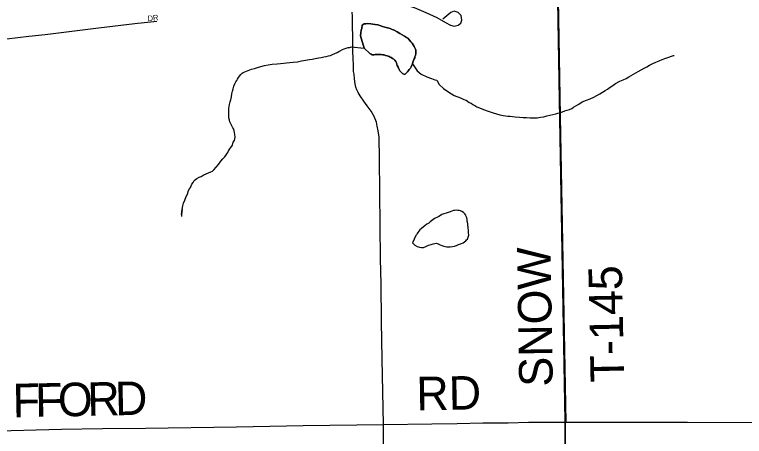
# Model space of a CAD drawing. Extents: x 0 to 34, y 0 to 22.
# Drawn here: x 3.494 to 4.731, y 18.837 to 19.552 of the extents above; entities that cross this region are included whole.
import ezdxf

# ---------------------------------------------------------------- set-up
doc = ezdxf.new("R2010")
doc.units = 0
for name, color, linetype in [('GM_X_Minor_Lake', 7, 'Continuous'), ('GM_X_Minor_River', 7, 'Continuous'), ('GM_X_Township', 7, 'Continuous'), ('GM_X_Township_Road', 7, 'Continuous'), ('GM_X_Township_Road_Text', 7, 'Continuous'), ('GM_X_Township_Subdivision', 7, 'Continuous'), ('GM_X_Township_Subdivision_Text', 7, 'Continuous')]:
    doc.layers.add(name, color=color, linetype=linetype)

msp = doc.modelspace()

# ---------------------------------------------------------------- linework, layer by layer
at = {"layer": 'GM_X_Minor_Lake'}
for points in [[(4.1715, 19.4767), (4.1722, 19.4786), (4.1725, 19.4805), (4.1736, 19.4824), (4.1739, 19.4858), (4.1742, 19.4889), (4.1742, 19.4915), (4.1738, 19.4934), (4.1726, 19.4957), (4.1714, 19.4976), (4.1694, 19.5006), (4.1678, 19.5032), (4.1655, 19.5058), (4.1635, 19.5084), (4.1604, 19.5118), (4.1585, 19.5132), (4.155, 19.5151), (4.1512, 19.5173), (4.1469, 19.5198), (4.1423, 19.5224), (4.1373, 19.5253), (4.1339, 19.5268), (4.1304, 19.5282), (4.1262, 19.5293), (4.1216, 19.5303), (4.1174, 19.5317), (4.1132, 19.5335), (4.1097, 19.5346), (4.1055, 19.5353), (4.1013, 19.5359), (4.0979, 19.5362), (4.093, 19.5365), (4.0895, 19.5364), (4.0865, 19.5364), (4.0831, 19.534), (4.0825, 19.5283), (4.0818, 19.5253), (4.0811, 19.5207), (4.0805, 19.5157), (4.0866, 19.4951)], [(4.0866, 19.4951), (4.0805, 19.5157), (4.0811, 19.5207), (4.0818, 19.5253), (4.0825, 19.5283), (4.0831, 19.534), (4.0865, 19.5364), (4.0895, 19.5364), (4.093, 19.5365), (4.0979, 19.5362), (4.1013, 19.5359), (4.1055, 19.5353), (4.1097, 19.5346), (4.1132, 19.5335), (4.1174, 19.5317), (4.1216, 19.5303), (4.1262, 19.5293), (4.1304, 19.5282), (4.1339, 19.5268), (4.1373, 19.5253), (4.1423, 19.5224), (4.1469, 19.5198), (4.1512, 19.5173), (4.155, 19.5151), (4.1585, 19.5132), (4.1604, 19.5118), (4.1635, 19.5084), (4.1655, 19.5058), (4.1678, 19.5032), (4.1694, 19.5006), (4.1714, 19.4976), (4.1726, 19.4957), (4.1738, 19.4934), (4.1742, 19.4915), (4.1742, 19.4889), (4.1739, 19.4858), (4.1736, 19.4824), (4.1725, 19.4805), (4.1722, 19.4786), (4.1715, 19.4767), (4.1704, 19.474), (4.1693, 19.4713), (4.1686, 19.4682), (4.1675, 19.4659), (4.166, 19.4632), (4.1649, 19.4613), (4.1631, 19.459), (4.1616, 19.4571), (4.1601, 19.4548), (4.1579, 19.4528), (4.1553, 19.4505), (4.1514, 19.4523), (4.1491, 19.4545), (4.1471, 19.4568), (4.1456, 19.4598), (4.144, 19.4628), (4.1428, 19.4658), (4.142, 19.468), (4.1412, 19.4699), (4.14, 19.4722), (4.1384, 19.4744), (4.1368, 19.4763), (4.1349, 19.4774), (4.1326, 19.4789), (4.1307, 19.4796), (4.1288, 19.4807), (4.1257, 19.4821), (4.123, 19.4828), (4.1207, 19.4835), (4.1184, 19.4839), (4.1154, 19.4842), (4.1123, 19.4845), (4.1097, 19.4844), (4.1074, 19.4844), (4.1055, 19.484), (4.1036, 19.4839), (4.1002, 19.4839), (4.0982, 19.4846), (4.0963, 19.4857), (4.0866, 19.4951)], [(4.0866, 19.4951), (4.0963, 19.4857), (4.0982, 19.4846), (4.1002, 19.4839), (4.1036, 19.4839), (4.1055, 19.484), (4.1074, 19.4844), (4.1097, 19.4844), (4.1123, 19.4845), (4.1154, 19.4842), (4.1184, 19.4839), (4.1207, 19.4835), (4.123, 19.4828), (4.1257, 19.4821), (4.1288, 19.4807), (4.1307, 19.4796), (4.1326, 19.4789), (4.1349, 19.4774), (4.1368, 19.4763), (4.1384, 19.4744), (4.14, 19.4722), (4.1412, 19.4699), (4.142, 19.468), (4.1428, 19.4658), (4.144, 19.4628), (4.1456, 19.4598), (4.1471, 19.4568), (4.1491, 19.4545), (4.1514, 19.4523), (4.1553, 19.4505), (4.1579, 19.4528), (4.1601, 19.4548), (4.1616, 19.4571), (4.1631, 19.459), (4.1649, 19.4613), (4.166, 19.4632), (4.1675, 19.4659), (4.1686, 19.4682), (4.1693, 19.4713), (4.1704, 19.474), (4.1715, 19.4767)], [(4.2614, 19.202), (4.2609, 19.2046), (4.2605, 19.2077), (4.2597, 19.2099), (4.2589, 19.2118), (4.2573, 19.2144), (4.255, 19.2167), (4.2519, 19.2181), (4.25, 19.2192), (4.2477, 19.2199), (4.2454, 19.2202), (4.2423, 19.2206), (4.2405, 19.2201), (4.2378, 19.2197), (4.2352, 19.2189), (4.2321, 19.2177), (4.2287, 19.2165), (4.2253, 19.2156), (4.2216, 19.2144), (4.2185, 19.2132), (4.2159, 19.2116), (4.2129, 19.21), (4.2099, 19.2081), (4.2069, 19.2069), (4.2031, 19.2041), (4.2009, 19.2026), (4.1986, 19.2006), (4.196, 19.1987), (4.193, 19.1967), (4.19, 19.1947), (4.1837, 19.1896), (4.1811, 19.1869), (4.1792, 19.185), (4.1777, 19.1827), (4.1762, 19.1807), (4.1751, 19.1788), (4.174, 19.1777), (4.174, 19.1773), (4.1686, 19.165)], [(4.1686, 19.165), (4.1725, 19.1613), (4.1763, 19.1591), (4.1802, 19.1576), (4.1836, 19.1573), (4.1874, 19.1574), (4.1912, 19.159), (4.1957, 19.161), (4.2002, 19.1623), (4.2036, 19.1635), (4.2063, 19.1639), (4.2093, 19.1644), (4.2131, 19.1629), (4.2154, 19.1618), (4.2185, 19.1604), (4.2216, 19.1597), (4.2239, 19.159), (4.2269, 19.1583), (4.2296, 19.1583), (4.2326, 19.1584), (4.2361, 19.1589), (4.2395, 19.1597), (4.2429, 19.1605), (4.2462, 19.1625), (4.2515, 19.1641), (4.2546, 19.1653), (4.2587, 19.1685), (4.2602, 19.1704), (4.262, 19.1716), (4.2638, 19.1781), (4.2637, 19.1823), (4.2633, 19.1845), (4.2632, 19.1868), (4.2628, 19.1902), (4.2627, 19.1921), (4.2623, 19.194), (4.2622, 19.1974), (4.2618, 19.2001), (4.2614, 19.202), (4.2609, 19.2046), (4.2605, 19.2077), (4.2597, 19.2099), (4.2589, 19.2118), (4.2573, 19.2144), (4.255, 19.2167), (4.2519, 19.2181), (4.25, 19.2192), (4.2477, 19.2199), (4.2454, 19.2202), (4.2423, 19.2206), (4.2405, 19.2201), (4.2378, 19.2197), (4.2352, 19.2189), (4.2321, 19.2177), (4.2287, 19.2165), (4.2253, 19.2156), (4.2216, 19.2144), (4.2185, 19.2132), (4.2159, 19.2116), (4.2129, 19.21), (4.2099, 19.2081), (4.2069, 19.2069), (4.2031, 19.2041), (4.2009, 19.2026), (4.1986, 19.2006), (4.196, 19.1987), (4.193, 19.1967), (4.19, 19.1947), (4.1837, 19.1896), (4.1811, 19.1869), (4.1792, 19.185), (4.1777, 19.1827), (4.1762, 19.1807), (4.1751, 19.1788), (4.174, 19.1777), (4.174, 19.1773), (4.1686, 19.165)], [(4.1686, 19.165), (4.1725, 19.1613), (4.1763, 19.1591), (4.1802, 19.1576), (4.1836, 19.1573), (4.1874, 19.1574), (4.1912, 19.159), (4.1957, 19.161), (4.2002, 19.1623), (4.2036, 19.1635), (4.2063, 19.1639), (4.2093, 19.1644), (4.2131, 19.1629), (4.2154, 19.1618), (4.2185, 19.1604), (4.2216, 19.1597), (4.2239, 19.159), (4.2269, 19.1583), (4.2296, 19.1583), (4.2326, 19.1584), (4.2361, 19.1589), (4.2395, 19.1597), (4.2429, 19.1605), (4.2462, 19.1625), (4.2515, 19.1641), (4.2546, 19.1653), (4.2587, 19.1685), (4.2602, 19.1704), (4.262, 19.1716), (4.2638, 19.1781), (4.2637, 19.1823), (4.2633, 19.1845), (4.2632, 19.1868), (4.2628, 19.1902), (4.2627, 19.1921), (4.2623, 19.194), (4.2622, 19.1974), (4.2618, 19.2001), (4.2614, 19.202)]]:
    msp.add_lwpolyline(points, dxfattribs=at)
at = {"layer": 'GM_X_Minor_River'}
for points in [[(4.0437, 19.4891), (4.046, 19.4903), (4.0498, 19.4926), (4.0528, 19.4938), (4.0562, 19.4951), (4.0596, 19.4959), (4.0622, 19.4963), (4.0645, 19.4971), (4.0866, 19.4951)], [(3.7774, 19.2097), (3.7779, 19.2218), (3.7773, 19.2131), (3.7779, 19.2218), (3.7792, 19.2276), (3.7807, 19.2322), (3.7828, 19.2375), (3.785, 19.2437), (3.7875, 19.249), (3.7886, 19.2525), (3.7908, 19.2567), (3.7923, 19.259), (3.7934, 19.2617), (3.7944, 19.2648), (3.7967, 19.2671), (3.7985, 19.2706), (3.803, 19.2741), (3.8067, 19.2764), (3.8101, 19.2777), (3.812, 19.2785), (3.815, 19.2804), (3.8188, 19.282), (3.8229, 19.284), (3.8267, 19.2856), (3.8293, 19.2868), (3.8316, 19.2891), (3.8398, 19.2977), (3.8438, 19.3035), (3.8472, 19.3073), (3.8498, 19.3104), (3.852, 19.3131), (3.8538, 19.3158), (3.8553, 19.3182), (3.8568, 19.3212), (3.859, 19.3247), (3.8608, 19.3266), (3.8634, 19.3309), (3.8648, 19.3358), (3.867, 19.3386), (3.8677, 19.3443), (3.8676, 19.3488), (3.8671, 19.3519), (3.8663, 19.3549), (3.8655, 19.3579), (3.8643, 19.3602), (3.8627, 19.3624), (3.8611, 19.3658), (3.8591, 19.3699), (3.8583, 19.3729), (3.8575, 19.3771), (3.8574, 19.3817), (3.8573, 19.3858), (3.8575, 19.3927), (3.8585, 19.3995), (3.8595, 19.4041), (3.8606, 19.4076), (3.8617, 19.4125), (3.8623, 19.4175), (3.8634, 19.4221), (3.8644, 19.4263), (3.8658, 19.4305), (3.8673, 19.4343), (3.8691, 19.4378), (3.8706, 19.4401), (3.872, 19.4424), (3.8739, 19.4451), (3.8754, 19.4478), (3.8776, 19.4505), (3.8798, 19.4528), (3.8817, 19.454), (3.8957, 19.4593), (3.9006, 19.4605), (3.9059, 19.4621), (3.9115, 19.4642), (3.9176, 19.4658), (3.924, 19.4667), (3.9305, 19.468), (3.9392, 19.4686), (3.9449, 19.4691), (3.9502, 19.4696), (3.9551, 19.4701), (3.9605, 19.4705), (3.9665, 19.4711), (3.9734, 19.472), (3.9806, 19.4736), (3.9874, 19.4749), (3.9938, 19.4758), (3.9984, 19.4763), (4.0014, 19.4768), (4.0037, 19.4772), (4.0063, 19.478), (4.0097, 19.4788), (4.0139, 19.4793), (4.0181, 19.4802), (4.0222, 19.481), (4.026, 19.4819), (4.0294, 19.4827), (4.0328, 19.4843), (4.037, 19.4859), (4.0407, 19.4879), (4.0437, 19.4891)], [(4.1686, 19.4682), (4.1764, 19.4566), (4.1834, 19.4511), (4.1926, 19.4463), (4.2007, 19.4435), (4.2064, 19.4413), (4.2099, 19.4406), (4.2135, 19.4335), (4.2208, 19.4264), (4.2301, 19.4206), (4.2393, 19.4147), (4.2501, 19.4107), (4.2555, 19.4082), (4.2593, 19.4071), (4.262, 19.4053), (4.2647, 19.4031), (4.2678, 19.4016), (4.2705, 19.3998), (4.2739, 19.3976), (4.2778, 19.3958), (4.2905, 19.3903), (4.2951, 19.3889), (4.3, 19.3871), (4.3054, 19.3853), (4.3108, 19.3836), (4.3165, 19.3818), (4.3219, 19.3808), (4.3264, 19.3801), (4.3302, 19.3798), (4.3341, 19.3795), (4.3379, 19.3792), (4.3424, 19.3785), (4.3501, 19.378), (4.3558, 19.3777), (4.3619, 19.3775), (4.368, 19.3772), (4.374, 19.377), (4.3798, 19.3771), (4.3854, 19.378), (4.3911, 19.3788), (4.396, 19.3805), (4.4013, 19.3817), (4.4063, 19.3826), (4.4112, 19.3838), (4.4146, 19.3847), (4.4184, 19.3855), (4.4225, 19.3871), (4.4267, 19.3887), (4.4308, 19.39), (4.4346, 19.3912), (4.4384, 19.3928), (4.4414, 19.3948), (4.4451, 19.3971), (4.4504, 19.3999), (4.456, 19.4038), (4.4636, 19.4066), (4.4696, 19.4094), (4.4756, 19.4122), (4.4809, 19.4146), (4.4862, 19.4174), (4.4907, 19.4205), (4.4952, 19.4233), (4.4989, 19.4257), (4.5034, 19.4288), (4.5079, 19.4319), (4.5128, 19.4351), (4.5199, 19.439), (4.5256, 19.4414), (4.5309, 19.4438), (4.5354, 19.4466), (4.5512, 19.4557), (4.556, 19.4584), (4.5609, 19.4612), (4.5658, 19.4636), (4.5703, 19.466), (4.5745, 19.4683), (4.5809, 19.4711), (4.5865, 19.4735), (4.5918, 19.4759), (4.5979, 19.478), (4.6031, 19.4796), (4.6073, 19.4812), (4.6107, 19.4824), (4.6118, 19.4825)]]:
    msp.add_lwpolyline(points, dxfattribs=at)
at = {"layer": 'GM_X_Township'}
for points in [[(9.1622, 19.7691), (8.817, 19.7645), (7.8005, 19.7395), (6.782, 19.7315), (5.8028, 19.7101), (4.4134, 19.6764), (4.4176, 19.4076), (4.4274, 18.8628), (4.4298, 18.3764)], [(4.4298, 18.3764), (4.4274, 18.8628), (4.4176, 19.4076), (4.4134, 19.6764), (4.0516, 19.6654), (3.407, 19.6503), (2.3622, 19.6335)]]:
    msp.add_lwpolyline(points, dxfattribs=at)
at = {"layer": 'GM_X_Township_Road'}
for points in [[(4.4288, 18.8614), (4.4191, 19.3797), (4.4149, 19.6447)], [(4.1191, 18.8574), (4.1171, 18.9681), (4.1159, 19.0321), (4.1156, 19.0958), (4.1145, 19.1381), (4.1124, 19.3074), (4.1119, 19.344), (4.1105, 19.3548), (4.1089, 19.3628), (4.1073, 19.3698), (4.1038, 19.379), (4.0982, 19.3884), (4.0917, 19.3972), (4.0858, 19.4053), (4.0801, 19.4142), (4.0766, 19.4198), (4.0742, 19.4244), (4.0723, 19.429), (4.0713, 19.4346), (4.0702, 19.443), (4.0694, 19.451), (4.0688, 19.4553), (4.0686, 19.4615), (4.0686, 19.4672), (4.0678, 19.4766), (4.0675, 19.4914), (4.0675, 19.5062), (4.0672, 19.5174), (4.0667, 19.5295), (4.0667, 19.539), (4.0667, 19.5494), (4.0662, 19.5562)], [(4.4288, 18.8614), (4.4905, 18.8612), (4.5804, 18.8612), (4.6346, 18.8612), (4.7563, 18.8607), (4.8626, 18.8612), (4.9823, 18.8623), (5.0923, 18.8628), (5.1769, 18.8635), (5.2427, 18.8635), (5.3405, 18.864), (5.4426, 18.8654), (5.4561, 18.8653)], [(3.3183, 18.8446), (3.3794, 18.8448), (3.4451, 18.8463), (3.5735, 18.8497), (3.6432, 18.8505), (3.7163, 18.8512), (3.8701, 18.8532), (3.983, 18.8554), (4.1191, 18.8574), (4.2011, 18.8586), (4.2441, 18.8588), (4.2875, 18.8601), (4.3307, 18.8604), (4.3653, 18.8614), (4.4041, 18.8614), (4.4288, 18.8614)], [(4.1243, 18.3764), (4.1238, 18.4443), (4.1229, 18.5453), (4.1214, 18.6302), (4.1203, 18.7501), (4.1196, 18.8165), (4.1191, 18.8574)]]:
    msp.add_lwpolyline(points, dxfattribs=at)
at = {"layer": 'GM_X_Township_Subdivision'}
for points in [[(4.0645, 19.5777), (4.085, 19.5779), (4.1092, 19.5771), (4.1345, 19.5739), (4.1503, 19.5699), (4.1713, 19.564), (4.1912, 19.5556), (4.2095, 19.547), (4.2245, 19.5387), (4.2331, 19.5338), (4.2393, 19.5322), (4.2461, 19.5341), (4.2504, 19.5376), (4.2522, 19.5427), (4.2512, 19.5503), (4.2461, 19.5556), (4.2391, 19.5575), (4.2334, 19.5556), (4.2202, 19.5441)], [(3.3875, 19.4703), (3.4055, 19.4716), (3.4161, 19.4731), (3.4242, 19.476), (3.4328, 19.4809), (3.4412, 19.489), (3.4532, 19.5016), (3.4599, 19.5055), (3.4697, 19.5087), (3.4808, 19.5107), (3.5182, 19.5151), (3.5462, 19.5181), (3.6365, 19.5292), (3.6981, 19.5365), (3.7352, 19.5407)]]:
    msp.add_lwpolyline(points, dxfattribs=at)

# ---------------------------------------------------------------- texts
at = {"layer": 'GM_X_Township_Road_Text'}
for s, height, rotation, p in [('SNOW', 0.05682, 90.9357, (4.4063, 18.9218)), ('T-145', 0.05682, 91.1238, (4.5272, 18.9291)), ('RD', 0.05682, 0.9925, (4.1755, 18.8812)), ('F', 0.0568, 1.0786, (3.4913, 18.8695)), ('F', 0.0568, 1.0786, (3.5296, 18.8702)), ('O', 0.0568, 1.0783, (3.568, 18.8709)), ('R', 0.0568, 1.08, (3.618, 18.8719)), ('D', 0.0568, 1.4198, (3.665, 18.8728))]:
    msp.add_text(s, height=height, rotation=rotation, dxfattribs=at).set_placement(p)
at = {"layer": 'GM_X_Township_Subdivision_Text'}
msp.add_text('DR', height=0.00947, rotation=6.3375, dxfattribs=at).set_placement((3.7201, 19.5405))

doc.saveas('drawing.dxf')
